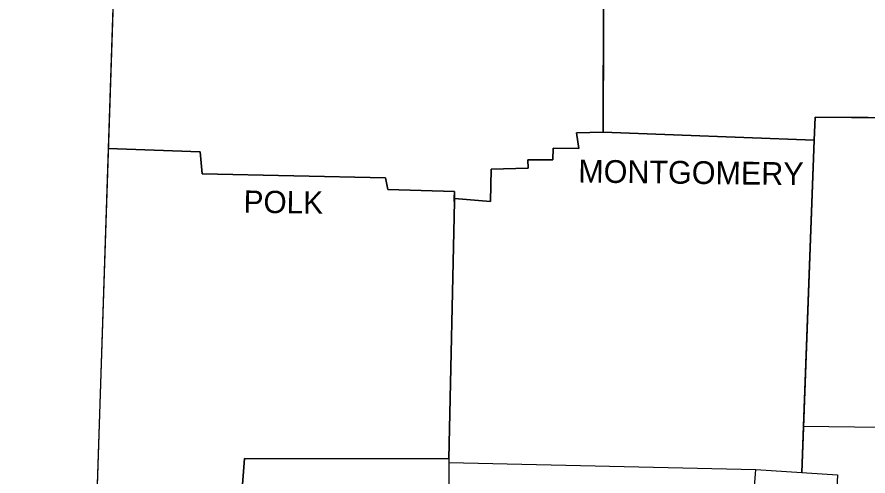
# Model space of a CAD drawing. Extents: x -13171 to 18763, y -8840 to 11152.
# Drawn here: x 10745 to 12315, y 7050 to 7898 of the extents above; entities that cross this region are included whole.
import ezdxf

# ---------------------------------------------------------------- set-up
doc = ezdxf.new("R2010")
doc.units = 0
for name, color, linetype in [('Level 1', 7, 'Continuous'), ('Level 2', 7, 'Continuous'), ('Level 48', 7, 'Continuous')]:
    doc.layers.add(name, color=color, linetype=linetype)

msp = doc.modelspace()

# ---------------------------------------------------------------- linework, layer by layer
at = {"layer": 'Level 1'}
for points in [[(10745.390580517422, 10312.988270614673), (10947.920791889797, 8686.876140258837), (10859.864178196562, 6032.458444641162)], [(12355.84820201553, 8380.634806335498), (12132.771447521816, 8379.656399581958), (12103.419243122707, 8354.21782231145), (12086.786327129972, 8315.081549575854), (12062.326156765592, 8317.038363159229), (12061.347749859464, 8294.535006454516), (12032.973952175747, 8291.59978588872), (12033.952359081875, 8271.053242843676), (11892.083370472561, 8274.966870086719), (11887.191336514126, 8259.312360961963), (11828.486927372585, 8257.35554737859), (11826.530113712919, 7684.987559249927), (11777.609772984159, 7684.009152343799), (11781.52340011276, 7654.656947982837), (11734.559872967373, 7655.635354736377), (11733.581466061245, 7634.110404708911), (11687.5963456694, 7634.110404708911), (11688.574752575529, 7618.455895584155), (11620.086275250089, 7616.499081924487), (11619.107868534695, 7556.816266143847), (11552.576204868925, 7562.686707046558), (11541.813729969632, 7081.31055302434), (11165.12710525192, 7082.2889597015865), (11156.32144397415, 6970.7505825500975)], [(12938.000258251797, 7826.856547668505), (12618.061229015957, 7836.640615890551), (12609.255567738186, 7710.426136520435), (12217.892840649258, 7712.382950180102), (12215.936027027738, 7670.3114568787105)], [(12215.936027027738, 7670.3114568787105), (11826.530113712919, 7684.987559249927)], [(12215.936027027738, 7670.3114568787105), (12193.265132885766, 7056.2259324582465)], [(10913.676553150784, 7654.656947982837), (11082.940932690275, 7648.786507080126), (11086.854559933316, 7607.693420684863), (11425.383318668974, 7600.844572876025), (11429.296945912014, 7579.319623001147), (11552.576204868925, 7575.405995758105), (11551.59779815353, 7556.816266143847)], [(12196.43269704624, 7142.025605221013), (12759.930217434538, 7134.144520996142), (12770.692692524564, 7227.093168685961), (12814.720999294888, 7227.093168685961), (12815.699406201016, 7305.365714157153), (13027.035278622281, 7302.430493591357), (13025.078465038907, 7255.466966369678), (13079.869246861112, 7251.5533390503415), (13079.869246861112, 7165.45353916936), (13115.09189216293, 7162.518318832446)], [(11541.813729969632, 7081.31055302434), (11541.813729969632, 6951.1824461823), (11563.338679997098, 6947.2688189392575), (11561.38186633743, 6825.946373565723), (11690.531566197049, 6816.162305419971), (11674.87705711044, 6169.435399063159), (11408.750402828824, 6176.284246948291)], [(11541.726566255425, 7074.515305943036), (12108.311277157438, 7061.742416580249)], [(12084.829513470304, 6880.7371554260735), (12082.87269988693, 6934.549530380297), (12098.527208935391, 6935.527937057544), (12108.311277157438, 7061.742416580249), (12258.985927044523, 7051.958348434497), (12255.072299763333, 6974.664209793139), (12449.775256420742, 6963.901734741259), (12450.75366332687, 6916.938207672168), (12626.866890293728, 6906.175732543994), (12657.1975017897, 6853.341764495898), (12638.607772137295, 6829.860000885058), (12647.413433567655, 6793.658948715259), (13285.334678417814, 6770.177185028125)]]:
    msp.add_lwpolyline(points, dxfattribs=at)
at = {"layer": 'Level 48'}
for p, q in [((10947.3638447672, 8670.087278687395), (10913.67835443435, 7654.656888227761)), ((11827.900316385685, 8085.771835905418), (11826.530113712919, 7684.987559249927)), ((11826.530113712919, 7684.987559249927), (11827.900316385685, 8085.771835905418)), ((11826.530113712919, 7684.987559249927), (11777.609772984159, 7684.009152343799)), ((11777.609772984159, 7684.009152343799), (11826.530113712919, 7684.987559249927)), ((12215.936027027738, 7670.3114568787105), (11826.530113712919, 7684.987559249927)), ((11826.530113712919, 7684.987559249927), (12215.936027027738, 7670.3114568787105)), ((10913.67835443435, 7654.656888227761), (10886.922977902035, 6848.1309279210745)), ((11733.581466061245, 7634.110404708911), (11687.5963456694, 7634.110404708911)), ((11620.086275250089, 7616.499081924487), (11619.107868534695, 7556.816266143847)), ((11552.576204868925, 7575.405995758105), (11552.576204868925, 7562.686707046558)), ((11619.107868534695, 7556.816266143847), (11552.576204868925, 7562.686707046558)), ((11552.576204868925, 7562.686707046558), (11619.107868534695, 7556.816266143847)), ((11541.813729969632, 7074.513340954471), (12108.311277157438, 7061.742416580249)), ((12108.311277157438, 7061.742416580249), (12193.265132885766, 7056.2259324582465))]:
    msp.add_line(p, q, dxfattribs=at)
for points in [[(12215.936027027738, 7670.3114568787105), (12217.892840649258, 7712.382950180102), (12351.147833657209, 7711.716675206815)], [(11777.609772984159, 7684.009152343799), (11781.52340011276, 7654.656947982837), (11734.559872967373, 7655.635354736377), (11733.581466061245, 7634.110404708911)], [(11734.559872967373, 7655.635354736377), (11781.52340011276, 7654.656947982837), (11777.609772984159, 7684.009152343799)], [(12193.265132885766, 7056.2259324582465), (12196.43269704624, 7142.025605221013), (12215.936027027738, 7670.3114568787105)], [(11425.383318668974, 7600.844572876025), (11086.854559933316, 7607.693420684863), (11082.940932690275, 7648.786507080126), (10913.678354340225, 7654.6568855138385)], [(10913.678354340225, 7654.6568855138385), (11082.940932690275, 7648.786507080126), (11086.854559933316, 7607.693420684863), (11425.383318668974, 7600.844572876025), (11429.296945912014, 7579.319623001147), (11552.576204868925, 7575.405995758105)], [(11619.107868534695, 7556.816266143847), (11620.086275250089, 7616.499081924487), (11688.574752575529, 7618.455895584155), (11687.5963456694, 7634.110404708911), (11733.581466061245, 7634.110404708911), (11734.559872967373, 7655.635354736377)], [(11687.5963456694, 7634.110404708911), (11688.574752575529, 7618.455895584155), (11620.086275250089, 7616.499081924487)], [(11552.576204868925, 7575.405995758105), (11429.296945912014, 7579.319623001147), (11425.383318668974, 7600.844572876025)], [(11551.59779815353, 7556.816266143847), (11551.908617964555, 7562.721843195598), (11552.576204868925, 7575.405995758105)], [(11169.040732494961, 6835.7304417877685), (11170.019139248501, 6960.966514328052), (11156.32144397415, 6970.7505825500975), (11165.12710525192, 7082.2889597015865), (11541.813729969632, 7081.31055302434), (11552.44453192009, 7556.7973351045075)], [(11552.576204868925, 7562.686707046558), (11552.44453192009, 7556.7973351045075), (11541.813729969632, 7081.31055302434)], [(11552.44453192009, 7556.7973351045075), (11551.59779815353, 7556.816266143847)], [(11541.813729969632, 7081.31055302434), (11541.813729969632, 7074.515305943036), (11541.813729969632, 7074.513340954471)]]:
    msp.add_lwpolyline(points, dxfattribs=at)

# ---------------------------------------------------------------- texts
at = {"layer": 'Level 2'}
for s, height, rotation, p in [('MONTGOMERY', 42.07344995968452, 359.29442221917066, (11780.544993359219, 7592.038911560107)), ('POLK', 41.0813454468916, 359.21517503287, (11163.170291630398, 7536.269723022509))]:
    msp.add_text(s, height=height, rotation=rotation, dxfattribs=at).set_placement(p)

doc.saveas('drawing.dxf')
